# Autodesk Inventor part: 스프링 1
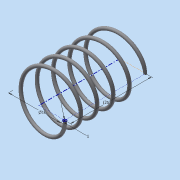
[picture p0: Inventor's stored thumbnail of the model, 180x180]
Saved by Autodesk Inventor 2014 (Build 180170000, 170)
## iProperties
Created: 2015-06
Part Number: 스프링 1
Material: 강철, 연강
Document SubType Name: Modeling
Designer: Administrator
Density: 7.86 g/cm^3
Appearance: 강철
Mass: 1.53535 g
Surface Area: 7.89042 cm^2
Volume: 0.195337 cm^3
Author: Administrator
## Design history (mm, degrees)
sketch "스케치1"
  geometry: L1 (0, 0)-(8, 0); L2 (8, 0)-(8, 21.5); L3 (8, 21.5)-(0, 21.5); L4 (0, 21.5)-(0, 0); C1 r 0.5 at (8, 0)
  constraints: 8 end point, 2 parallel, 1 centre point, 1 coincident, 1 horizontal, 1 perpendicular
  dimensions: "d0" = 1 diameter of C1; "d1" = 16 diameter of L2 L4; "d2" = 21.5 distance of L1.end L2.end (derived)
feature "코일1" pitch "d3" = 10; turns "d5" = 5; dims "d4" = 21.5 (= d2), "d6" = 0, angle "d7" = 90 deg, angle "d8" = 90 deg, "d9" = 0, "d10" = 0
sketch "스케치2"
  geometry: L1 (-8.5, 0)-(-7.5, 0) reference; L2 (-8.5, 0)-(-7.5, 0) reference; 1 further point
  constraints: 2 horizontal alignment
extrude "돌출1" cut sketch "스케치2" stored distance "d11" = 10; taper "d12" = 0 deg
node "작업 평면1"
sketch "스케치3"
  geometry: L1 (8.5, 0)-(7.5, 0) reference; 1 further point
  constraints: 1 horizontal alignment
extrude "돌출2" cut sketch "스케치3" stored distance "d14" = 10; taper "d15" = 0 deg
node "솔리드1"
node "절단 모서리 투영1"
node "절단 모서리 투영2"
node "절단 모서리 투영3"
other parameters: "d13" = -21.5 (= -d2)
